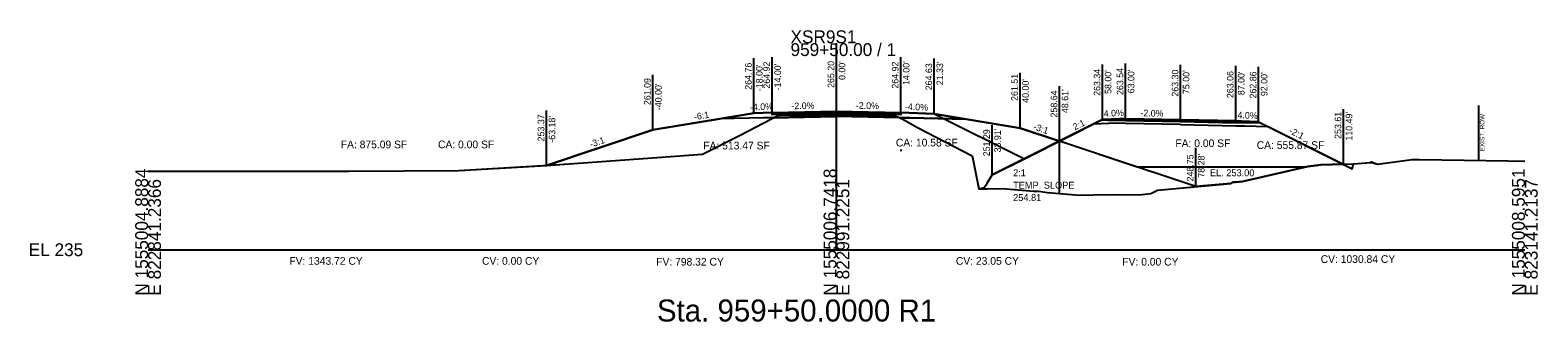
# Model space of a CAD drawing. Extents: x -26 to 823017, y -16 to 1558356.
# Drawn here: x -25.7 to 302.8, y 7484.3 to 7547.8 of the extents above; entities that cross this region are included whole.
import ezdxf

# ---------------------------------------------------------------- set-up
doc = ezdxf.new("R2010")
doc.units = 0
for name, color, linetype in [('ASPHALT_19MM1', 7, 'Continuous'), ('ASPHALT_9_5MM1', 7, 'Continuous'), ('CONST_DCH', 7, 'Continuous'), ('CONST_LV3', 7, 'Continuous'), ('Default', 7, 'Continuous'), ('Draft_XS_Grid', 7, 'Continuous'), ('Draft_XS_Text', 7, 'Continuous'), ('DTM_CORRIDOR', 7, 'Continuous'), ('DTM_P_FINISHED_GRADE2', 7, 'Continuous'), ('DTM_TEMP_DROP', 7, 'Continuous'), ('DTM_X_GROUND', 7, 'Continuous'), ('PROFILES_DCH_2', 7, 'Continuous'), ('SLOPE_STAKES_FILL', 7, 'Continuous'), ('XS_CELL', 7, 'Continuous'), ('XS_M_SHAPES_EARTHWORK', 7, 'Continuous'), ('XS_P_ASPHALT', 7, 'Continuous'), ('XS_P_DR_GRAVEL', 7, 'Continuous'), ('XS_P_GROUND', 7, 'Continuous'), ('XS_P_NULL_POINT', 7, 'Continuous'), ('XS_P_SHOULDER', 7, 'Continuous'), ('XS_P_SUBGRADE_GRANULAR', 7, 'Continuous'), ('XS_P_SUBGRADE_MILLING', 7, 'Continuous'), ('XS_P_SUBGRADE_UNDERCUT', 7, 'Continuous'), ('XS_P_TX_CLEARZONE', 7, 'Continuous'), ('XS_P_TX_FS_BS', 7, 'Continuous'), ('XS_SHEET_EW_TX_AREA', 7, 'Continuous'), ('XS_SHEET_EW_TX_VOLUME', 7, 'Continuous'), ('XS_X_ROW', 7, 'Continuous')]:
    doc.layers.add(name, color=color, linetype=linetype)

msp = doc.modelspace()

# ---------------------------------------------------------------- linework, layer by layer
at = {"layer": 'ASPHALT_19MM1'}
for points in [[(136, 7529.63), (150, 7529.91), (150, 7529.91), (150, 7529.91), (164, 7529.63), (164, 7529.42), (150, 7529.7), (150, 7529.7), (150, 7529.7), (136, 7529.42), (136, 7529.63)], [(213, 7528.16), (225, 7527.92), (237, 7527.68), (237, 7527.89), (225, 7528.13), (213, 7528.37), (213, 7528.16)]]:
    msp.add_lwpolyline(points, dxfattribs=at)
at = {"layer": 'ASPHALT_9_5MM1'}
msp.add_lwpolyline([(136, 7529.92), (150, 7530.2), (150, 7530.2), (150, 7530.2), (164, 7529.92), (164, 7529.8), (150, 7530.08), (150, 7530.08), (150, 7530.08), (136, 7529.8), (136, 7529.92)], dxfattribs=at)
at = {"layer": 'CONST_DCH'}
msp.add_lwpolyline([(213, 7528.37), (225, 7528.13), (237, 7527.89), (237, 7528.06), (225, 7528.3), (213, 7528.54), (213, 7528.37)], dxfattribs=at)
at = {"layer": 'CONST_LV3'}
for points in [[(150, 7530.2), (164, 7529.92)], [(110, 7526.09), (124.59, 7528.53), (124.59, 7528.53)], [(171.33, 7529.63), (171.33, 7529.63), (164, 7529.92)], [(190, 7526.51), (190, 7526.51), (178.28, 7528.47)], [(183.91, 7516.29), (191.41, 7520.04), (208, 7528.34), (211.75, 7528.49), (213, 7528.54)], [(198.61, 7523.64), (198.61, 7523.64), (208, 7528.34), (209.25, 7528.39), (213, 7528.54), (215.99, 7528.48), (225, 7528.3), (234.01, 7528.12), (237, 7528.06), (240.75, 7527.91), (242, 7527.86), (245.97, 7525.87), (254.74, 7521.49), (255.69, 7521.01), (262.41, 7517.65), (262.57, 7518.38), (262.65, 7518.74), (266.36, 7519), (266.6, 7519.15), (266.6, 7519.15), (267.89, 7518.67), (275.45, 7519.66), (276.99, 7519.67), (286.78, 7519.51), (296.32, 7519.37), (300, 7519.31)], [(242, 7527.86), (260.49, 7518.61)], [(164, 7521.81), (164, 7521.74), (164, 7521.7), (164, 7521.58), (164, 7521.45)], [(0, 7517.14), (3.13, 7517.14), (15.53, 7517.14), (21.81, 7517.14), (43.84, 7517.11), (67.73, 7517.24), (86.82, 7518.37), (86.82, 7518.37)]]:
    msp.add_lwpolyline(points, dxfattribs=at)
at = {"layer": 'Default'}
msp.add_lwpolyline([(136, 7529.8), (150, 7530.08), (150, 7530.08), (150, 7530.08), (164, 7529.8), (164, 7529.63), (150, 7529.91), (150, 7529.91), (150, 7529.91), (136, 7529.63), (136, 7529.8)], dxfattribs=at)
at = {"layer": 'DTM_P_FINISHED_GRADE2'}
msp.add_lwpolyline([(86.82, 7518.37), (86.82, 7518.37), (110, 7526.09), (132, 7529.76), (136, 7529.92), (150, 7530.2), (164, 7529.92), (171.33, 7529.63), (190, 7526.51), (198.61, 7523.64)], dxfattribs=at)
at = {"layer": 'DTM_X_GROUND'}
for points in [[(0, 7517.14), (3.13, 7517.14), (15.53, 7517.14), (21.81, 7517.14), (43.84, 7517.11), (67.73, 7517.24), (86.82, 7518.37), (86.82, 7518.37), (86.82, 7518.37), (110, 7526.09), (110, 7526.09), (132, 7529.76), (132, 7529.76), (136, 7529.92), (150, 7530.2), (150, 7530.2), (150, 7530.2), (164, 7529.92), (171.33, 7529.63), (171.33, 7529.63), (190, 7526.51), (190, 7526.51), (198.61, 7523.64), (198.61, 7523.64), (198.61, 7523.64), (208, 7528.34), (209.25, 7528.39), (213, 7528.54), (215.99, 7528.48), (225, 7528.3), (234.01, 7528.12), (237, 7528.06), (240.75, 7527.91), (242, 7527.86), (245.97, 7525.87), (254.74, 7521.49), (255.69, 7521.01), (262.41, 7517.65), (262.57, 7518.38), (262.65, 7518.74), (266.36, 7519), (266.6, 7519.15), (266.6, 7519.15), (267.89, 7518.67), (275.45, 7519.66), (276.99, 7519.67), (286.78, 7519.51), (296.32, 7519.37), (300, 7519.31)], [(0, 7517.14), (3.13, 7517.14), (15.53, 7517.14), (21.81, 7517.14), (43.84, 7517.11), (67.73, 7517.24), (89.7, 7518.54), (95.81, 7518.98), (107.89, 7519.86), (120.82, 7520.8), (128.89, 7524.91), (135.96, 7528.58), (136.73, 7528.96), (137.3, 7529.22), (143.55, 7529.32), (150.12, 7529.43), (158.72, 7529.24), (162.86, 7529.15), (163.52, 7528.88), (164.34, 7528.53), (167.67, 7526.64), (179.61, 7520.44), (179.64, 7520.2), (181.05, 7513.23), (182.81, 7513.26), (186.15, 7513.31), (193, 7512.73), (194.09, 7512.73), (196.02, 7512.47), (203, 7511.92), (206.07, 7511.98), (210.41, 7512), (215.99, 7511.95), (218.48, 7512.23), (219.96, 7513.01), (235.94, 7514.44), (236.36, 7514.69), (236.98, 7514.75), (238.47, 7514.89), (252.74, 7518.14), (255.58, 7518.46), (262.57, 7518.73), (266.6, 7519.02), (267.89, 7518.67), (275.45, 7519.66), (276.99, 7519.67), (286.78, 7519.51), (296.32, 7519.37), (300, 7519.31)], [(0, 7517.14), (3.13, 7517.14), (15.53, 7517.14), (21.81, 7517.14), (43.84, 7517.11), (67.73, 7517.24), (89.7, 7518.54), (95.81, 7518.98), (107.89, 7519.86), (120.82, 7520.8), (128.89, 7524.91), (135.96, 7528.58), (136.73, 7528.96), (137.3, 7529.22), (143.55, 7529.32), (150.12, 7529.43), (158.72, 7529.24), (162.86, 7529.15), (163.52, 7528.88), (164.34, 7528.53), (167.67, 7526.64), (179.61, 7520.44), (179.64, 7520.2), (181.05, 7513.23), (182.21, 7513.58), (182.81, 7514.53), (183.91, 7516.29), (189.12, 7518.9), (191.14, 7519.91), (191.41, 7520.04), (208, 7528.34), (209.25, 7528.39), (213, 7528.54), (215.99, 7528.48), (225, 7528.3), (234.01, 7528.12), (237, 7528.06), (240.75, 7527.91), (242, 7527.86), (245.97, 7525.87), (254.74, 7521.49), (255.69, 7521.01), (262.41, 7517.65), (262.57, 7518.38), (262.65, 7518.74), (266.36, 7519), (266.6, 7519.15), (266.6, 7519.15), (267.89, 7518.67), (275.45, 7519.66), (276.99, 7519.67), (286.78, 7519.51), (296.32, 7519.37), (300, 7519.31)]]:
    msp.add_lwpolyline(points, dxfattribs=at)
at = {"layer": 'XS_CELL'}
for p, q in [((150, 7500), (150, 7545)), ((0, 7500), (150, 7500)), ((150, 7500), (300, 7500))]:
    msp.add_line(p, q, dxfattribs=at)
at = {"layer": 'XS_M_SHAPES_EARTHWORK'}
for points in [[(86.82, 7518.37), (89.7, 7518.54), (95.81, 7518.98), (107.89, 7519.86), (120.82, 7520.8), (128.89, 7524.91), (135.96, 7528.58), (136.33, 7528.76), (136, 7528.75), (134, 7528.71), (124.59, 7528.53), (110, 7526.09)], [(136.33, 7528.76), (136.73, 7528.96), (137.3, 7529.22), (143.55, 7529.32), (150.12, 7529.43), (158.72, 7529.24), (162.86, 7529.15), (163.52, 7528.88), (163.81, 7528.76), (150, 7529.03)], [(163.81, 7528.76), (164.34, 7528.53), (167.67, 7526.64), (179.61, 7520.44), (179.64, 7520.2), (181.05, 7513.23), (182.81, 7513.26), (186.15, 7513.31), (193, 7512.73), (194.09, 7512.73), (196.02, 7512.47), (198.61, 7512.27), (198.61, 7523.64), (190, 7526.51), (178.28, 7528.47), (166, 7528.71), (164, 7528.75)]]:
    msp.add_lwpolyline(points, close=True, dxfattribs=at)
at = {"layer": 'XS_P_DR_GRAVEL'}
for points in [[(211.75, 7528.49), (208, 7528.34), (207.96, 7528.32), (207.86, 7528.27), (209.14, 7528.24), (213, 7528.16), (213, 7528.44), (213, 7528.54), (211.75, 7528.49)], [(238.25, 7528.01), (242, 7527.86), (242.14, 7527.79), (242.57, 7527.57), (238.39, 7527.66), (237, 7527.68), (237, 7527.96), (237, 7528.06), (238.25, 7528.01)]]:
    msp.add_lwpolyline(points, dxfattribs=at)
at = {"layer": 'XS_P_GROUND'}
msp.add_line((171.33, 7529.63), (190.95, 7519.81), dxfattribs=at)
for points in [[(132, 7529.76), (110, 7526.09), (86.82, 7518.37)], [(198.61, 7523.64), (198.61, 7523.64), (190, 7526.51), (190, 7526.51), (171.33, 7529.63)], [(228.28, 7513.75), (190, 7526.52), (190, 7526.52), (190, 7526.52), (171.33, 7529.63)], [(208, 7528.34), (183.91, 7516.29)], [(242, 7527.86), (262.41, 7517.65)], [(260.49, 7518.65), (255.58, 7518.46), (255.58, 7518.46), (252.74, 7518.14), (252.74, 7518.14), (238.47, 7514.89), (238.47, 7514.89), (238.47, 7514.89), (236.98, 7514.75), (236.36, 7514.69), (236.36, 7514.69), (235.94, 7514.44), (228.28, 7513.75), (228.28, 7513.75), (228.28, 7513.75)], [(228.28, 7513.75), (228.28, 7513.75), (228.28, 7513.75), (235.94, 7514.44), (236.36, 7514.69), (236.36, 7514.69), (236.98, 7514.75), (238.47, 7514.89), (238.47, 7514.89), (238.47, 7514.89), (252.74, 7518.14), (252.74, 7518.14), (255.58, 7518.46), (255.58, 7518.46), (260.49, 7518.65)]]:
    msp.add_lwpolyline(points, dxfattribs=at)
at = {"layer": 'XS_P_SHOULDER'}
for points in [[(136, 7529.92), (132, 7529.76)], [(164, 7529.92), (171.33, 7529.63)], [(208, 7528.34), (211.75, 7528.49), (213, 7528.54)], [(242, 7527.86), (238.25, 7528.01), (237, 7528.06)]]:
    msp.add_lwpolyline(points, dxfattribs=at)
at = {"layer": 'XS_P_SUBGRADE_GRANULAR'}
for points in [[(136, 7528.75), (134, 7528.71), (124.59, 7528.53)], [(136, 7528.75), (150, 7529.03), (150, 7529.03)], [(164, 7528.75), (150, 7529.03), (150, 7529.03)], [(164, 7528.75), (166, 7528.71), (178.28, 7528.47)], [(213, 7527.5), (211, 7527.54), (206, 7527.34)], [(225, 7527.26), (213, 7527.5)], [(225, 7527.26), (237, 7527.02)], [(237, 7527.02), (239, 7526.98), (243.96, 7526.88)]]:
    msp.add_lwpolyline(points, dxfattribs=at)
at = {"layer": 'XS_P_SUBGRADE_UNDERCUT'}
msp.add_lwpolyline([(215.55, 7518), (198.61, 7523.64), (208, 7528.34), (213, 7528.54), (225, 7528.3), (237, 7528.06), (242, 7527.86), (260.42, 7518.65), (259.07, 7518.59), (255.58, 7518.46), (252.74, 7518.14), (252.11, 7518)], close=True, dxfattribs=at)
at = {"layer": 'XS_P_TX_CLEARZONE'}
for p, q in [((132, 7529.76), (132, 7541.76)), ((136, 7529.92), (136, 7541.92)), ((150, 7530.2), (150, 7542.2)), ((164, 7529.92), (164, 7541.92)), ((171.33, 7529.63), (171.33, 7541.63)), ((208, 7528.34), (208, 7540.34)), ((213, 7528.54), (213, 7540.54)), ((225, 7528.3), (225, 7540.3)), ((237, 7528.06), (237, 7540.06)), ((242, 7527.86), (242, 7539.86)), ((110, 7526.09), (110, 7538.09)), ((190, 7526.51), (190, 7538.51)), ((198.61, 7523.64), (198.61, 7535.64)), ((86.82, 7518.37), (86.82, 7530.37)), ((260.49, 7518.61), (260.49, 7530.61)), ((183.91, 7516.29), (183.91, 7527.16)), ((228.28, 7513.75), (228.28, 7522.19))]:
    msp.add_line(p, q, dxfattribs=at)
at = {"layer": 'XS_X_ROW'}
msp.add_line((290, 7519.46), (290, 7531.46), dxfattribs=at)

# ---------------------------------------------------------------- texts
at = {"layer": 'CONST_DCH'}
for p in [(260.42, 7518.49), (262.33, 7517.53), (183.84, 7516.17)]:
    msp.add_text('X', height=0.24, dxfattribs=at).set_placement(p)
at = {"layer": 'Draft_XS_Grid'}
msp.add_text('-', height=0.0001, dxfattribs=at).set_placement((0, 7500))
at = {"layer": 'Draft_XS_Text'}
msp.add_text('Sta. 959+50.0000 R1', height=4.8, dxfattribs=at).set_placement((110.88, 7484.35))
at = {"layer": 'DTM_CORRIDOR'}
for p in [(212.92, 7528.42), (224.92, 7528.18), (236.92, 7527.94)]:
    msp.add_text('X', height=0.24, dxfattribs=at).set_placement(p)
at = {"layer": 'DTM_TEMP_DROP'}
for p in [(135.92, 7529.8), (149.92, 7530.08), (163.92, 7529.8)]:
    msp.add_text('X', height=0.24, dxfattribs=at).set_placement(p)
at = {"layer": 'PROFILES_DCH_2'}
for p in [(171.25, 7529.51), (189.92, 7526.4), (260.42, 7518.49), (228.21, 7513.63)]:
    msp.add_text('X', height=0.24, dxfattribs=at).set_placement(p)
at = {"layer": 'SLOPE_STAKES_FILL'}
for p in [(198.53, 7523.52), (86.75, 7518.25)]:
    msp.add_text('X', height=0.24, dxfattribs=at).set_placement(p)
at = {"layer": 'XS_CELL'}
for s, p in [('XSR9S1', (140, 7545)), ('959+50.00 / 1', (140, 7542.2)), ('EL 235', (-26, 7498.6))]:
    msp.add_text(s, height=2.8, dxfattribs=at).set_placement(p)
for s, p in [('N 1555004.8884', (0, 7490)), ('N 1555006.7418', (150, 7490)), ('N 1555008.5951', (300, 7490)), ('E 822841.2366', (2.8, 7490)), ('E 822991.2251', (152.8, 7490)), ('E 823141.2137', (302.8, 7490))]:
    msp.add_text(s, height=2.8, rotation=90, dxfattribs=at).set_placement(p)
at = {"layer": 'XS_P_ASPHALT'}
for p in [(262.33, 7517.53), (183.84, 7516.17)]:
    msp.add_text('X', height=0.24, dxfattribs=at).set_placement(p)
at = {"layer": 'XS_P_GROUND'}
for s, p in [('2:1', (188.5, 7516.01)), ('TEMP. SLOPE', (188.5, 7513.31)), ('254.81', (188.5, 7510.61))]:
    msp.add_text(s, height=1.5, dxfattribs=at).set_placement(p)
at = {"layer": 'XS_P_NULL_POINT'}
for p in [(198.53, 7523.52), (86.75, 7518.25)]:
    msp.add_text('X', height=0.24, dxfattribs=at).set_placement(p)
at = {"layer": 'XS_P_SHOULDER'}
for p in [(207.92, 7528.22), (241.92, 7527.74), (109.92, 7525.97), (189.92, 7526.39)]:
    msp.add_text('X', height=0.24, dxfattribs=at).set_placement(p)
at = {"layer": 'XS_P_SUBGRADE_MILLING'}
for p in [(131.92, 7529.64), (171.25, 7529.51)]:
    msp.add_text('X', height=0.24, dxfattribs=at).set_placement(p)
at = {"layer": 'XS_P_SUBGRADE_UNDERCUT'}
msp.add_text('EL. 253.00', height=1.5, dxfattribs=at).set_placement((231.38, 7516.01))
at = {"layer": 'XS_P_TX_CLEARZONE'}
for s, p in [('264.76', (131.52, 7534.86)), ("-18.00'", (133.92, 7534.55)), ('264.92', (135.52, 7535.1)), ("-14.00'", (137.92, 7534.71)), ('265.20', (149.52, 7535.25)), ("0.00'", (151.92, 7536.99)), ('264.92', (163.52, 7535.1)), ("14.00'", (165.92, 7535.89)), ('264.63', (170.85, 7534.74)), ("21.33'", (173.25, 7535.83)), ('261.09', (109.52, 7531.51)), ('261.51', (189.52, 7532.42)), ("40.00'", (191.92, 7532.01)), ('263.34', (207.52, 7533.52)), ("58.00'", (209.92, 7533.95)), ('263.54', (212.52, 7533.72)), ("63.00'", (214.92, 7534.08)), ('263.30', (224.52, 7533.35)), ("75.00'", (226.92, 7533.91)), ('263.06', (236.52, 7533.04)), ("87.00'", (238.92, 7533.67)), ('262.86', (241.52, 7532.96)), ("92.00'", (243.92, 7533.47)), ("-40.00'", (111.92, 7530.41)), ('258.64', (198.13, 7528.82)), ("48.61'", (200.53, 7529.77)), ('253.37', (86.34, 7523.61)), ("-63.18'", (88.74, 7523.32)), ('253.61', (260.01, 7524.15)), ("110.49'", (262.41, 7523.77)), ('251.29', (183.43, 7520.36)), ("33.91'", (185.83, 7521.2)), ('248.75', (227.8, 7514.87)), ("78.28'", (230.2, 7515.7))]:
    msp.add_text(s, height=1.44, rotation=90, dxfattribs=at).set_placement(p)
at = {"layer": 'XS_P_TX_FS_BS'}
for s, rotation, p in [('-6:1', 9.4642, (119.08, 7528.21)), ('-4.0%', 2.2906, (131.18, 7530.33)), ('-2.0%', 1.1458, (140.2, 7530.6)), ('-2.0%', 358.8542, (154.22, 7530.72)), ('-4.0%', 357.7094, (164.9, 7530.49)), ('4.0%', 2.2906, (208.27, 7528.95)), ('-2.0%', 358.8542, (216.22, 7529.07)), ('-4.0%', 357.7094, (236.73, 7528.67)), ('-3:1', 341.563, (192.78, 7526.22)), ('2:1', 26.5651, (201.94, 7525.98)), ('-3:1', 18.4332, (96.5, 7522.23)), ('-2:1', 333.4349, (248.46, 7525.47))]:
    msp.add_text(s, height=1.44, rotation=rotation, dxfattribs=at).set_placement(p)
at = {"layer": 'XS_SHEET_EW_TX_AREA'}
for s, p in [('FA: 875.09 SF', (41.99, 7522.1)), ('CA: 0.00 SF', (63.18, 7522.1)), ('FA: 513.47 SF', (120.99, 7521.85)), ('CA: 10.58 SF', (162.95, 7522.5)), ('FA: 0.00 SF', (223.85, 7522.36)), ('CA: 555.87 SF', (241.58, 7521.96))]:
    msp.add_text(s, height=1.68, dxfattribs=at).set_placement(p)
at = {"layer": 'XS_SHEET_EW_TX_VOLUME'}
for s, p in [('FV: 1343.72 CY', (30.79, 7496.72)), ('CV: 0.00 CY', (72.76, 7496.72)), ('FV: 798.32 CY', (110.72, 7496.54)), ('CV: 23.05 CY', (176.03, 7496.72)), ('FV: 0.00 CY', (212.29, 7496.54)), ('CV: 1030.84 CY', (255.52, 7497.12))]:
    msp.add_text(s, height=1.68, dxfattribs=at).set_placement(p)
at = {"layer": 'XS_X_ROW'}
msp.add_text('EXIST. ROW', height=1, rotation=90, dxfattribs=at).set_placement((291.2, 7521.46))

doc.saveas('drawing.dxf')
